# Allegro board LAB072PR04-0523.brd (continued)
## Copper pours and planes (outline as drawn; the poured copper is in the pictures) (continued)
BST_5V on TOP (solid shape): 51.49,27.49 51.49,26.47 51.43,26.41 51.43,25.01 51.3,24.88 50.66,24.88 50.44,25.1 50.44,25.61 51.24,26.41 51.24,27.42 51.36,27.55 51.43,27.55
CHAGER_SRC on TOP (solid shape): 40.19,42.47 40.19,34.98 39.81,34.6 39.81,29.26 39.68,29.14 35.36,29.14 35.23,29.26 35.23,33.84 35.62,34.22 36.89,34.22 37.14,34.47 37.14,35.49 37.27,35.61 37.27,39.42 37.01,39.68 30.92,39.68 30.54,40.06 30.54,42.34 30.92,42.73 39.93,42.73
CHAGER_SRC on BOTTOM (solid shape): 40.82,39.17 40.82,35.61 39.81,34.6 37.39,34.6 37.14,34.85 37.14,39.17 36.76,39.55 31.04,39.55 30.54,40.06 30.54,41.58 31.04,42.09 33.2,42.09 33.84,42.73 37.27,42.73
CHG_LGATE on TOP (solid shape): 28.38,35.99 28.38,34.98 28.12,34.72 26.85,34.72 26.6,34.98 26.6,35.99 26.85,36.25 28.12,36.25
CHG_LGATE on BOTTOM (solid shape): 31.69,17.86 31.69,17.02 31.95,16.77 31.95,15.78 31.89,15.73 31.8,15.73 31.74,15.79 31.74,16.57 31.51,16.8 31.32,16.8 31.17,16.95 31.17,17.87 31.26,17.97 31.58,17.97
CHG_LGATE on IN3 (solid shape): 31.42,19.23 31.42,18.34 31.81,17.96 31.81,16.94 31.55,16.69 31.04,16.69 30.41,17.33 30.41,19.61 31.04,19.61
CHG_LGATE on IN3: 27.11,33.84 27.11,34.47 26.6,34.98 26.6,35.99 26.85,36.25 27.87,36.25 28.12,35.99 28.12,33.96 28,33.84
CHG_SW on TOP (solid shape): 34.54,18.98 34.54,17.26 34.22,16.94 33.9,16.94 33.84,17.01 33.84,17.96 33.52,18.28 33.52,18.98 33.58,19.04 34.47,19.04
CHG_SW on TOP (solid shape): 34.6,33.71 34.6,30.66 34.35,30.41 33.2,30.41 32.82,30.03 32.82,28.5 33.08,28.25 34.8,28.25 35.23,27.82 35.23,23.55 34.85,23.17 29.52,23.17 29.14,23.55 29.14,24.44 27.36,26.22 27.36,33.84 27.61,34.09 34.22,34.09
CHG_SW on BOTTOM (solid shape): 34.36,17.99 34.36,17.02 34.08,16.75 33.74,16.75 33.55,16.55 33.55,15.79 33.49,15.73 33.4,15.73 33.34,15.78 33.34,16.6 33.83,17.09 33.83,17.98 33.95,18.1 34.25,18.1
CHG_SW on BOTTOM (solid shape): 33.58,32.92 33.58,30.79 33.05,30.25 33.05,28.48 33.84,27.69 38.49,27.69 38.92,27.26 38.92,21.77 38.28,21.14 31.93,21.14 31.3,21.77 31.3,32.82 31.73,33.25 33.25,33.25
CHG_SW on IN1 (solid shape): 34.85,17.07 34.6,16.82 33.96,16.82 33.84,16.94 33.84,19.74 34.85,19.74
CHG_SW on IN1 (solid shape): 38.03,22.91 38.03,22.28 37.77,22.02 36.57,22.02 36.21,21.66 35.92,21.66 35.47,22.12 35.47,22.38 36.13,23.04 37.9,23.04
CHG_UGATE on TOP (solid shape): 34.54,29.71 34.54,28.56 34.41,28.44 33.39,28.44 33.14,28.69 33.14,29.58 33.39,29.83 34.41,29.83
CHG_UGATE on BOTTOM (solid shape): 33.59,18.02 33.59,17.09 33.14,16.65 33.14,15.79 33.09,15.73 33,15.73 32.94,15.79 32.94,16.9 33.07,17.02 33.07,17.99 33.18,18.1 33.51,18.1
CHG_UGATE on IN3 (solid shape): 33.71,18.98 33.71,16.94 33.58,16.82 33.2,16.82 33.08,16.94 33.08,17.33 32.89,17.51 32.89,19.04 33.08,19.23 33.46,19.23
CHG_UGATE on IN3: 34.47,29.26 33.33,29.26 33.08,29.01 33.08,28.5 33.33,28.25 33.96,28.25 34.73,27.48 35.12,27.48 35.44,27.8 35.44,28.3
DH_1.35V on TOP (solid shape): 68.64,33 68.64,32.06 68.51,31.93 67.62,31.93 67.49,32.06 67.49,32.54 68.03,33.07 68.56,33.07
DH_1.35V on BOTTOM (solid shape): 62.03,33.58 62.03,33.07 61.51,32.55 60.91,32.55 60.87,32.52 59.88,32.52 59.82,32.58 59.82,32.66 59.88,32.72 60.79,32.72 61.4,33.32 61.4,33.58 61.52,33.71 61.9,33.71
DH_1.35V on IN3 (solid shape): 68.79,32.59 68.79,31.7 68.66,31.57 67.64,31.57 66.88,32.34 66.5,32.34 66.5,33.1 68.28,33.1
DH_1.35V on IN3: 61.82,33.87 60.89,32.95 60.89,32.57 61.14,32.31 61.4,32.31 62.39,33.3 62.39,33.61 62.12,33.87
DL_1.35V on BOTTOM (solid shape): 60.43,34.77 60.43,33.88 59.92,33.37 59.92,33.37 59.75,33.2 59.59,33.2 59.54,33.24 59.54,34.2 59.92,34.58 59.92,34.77 60.05,34.9 60.3,34.9
DL_1.35V on IN3 (solid shape): 60.68,33.81 60.56,33.68 60.02,33.68 59.92,33.78 59.92,35.61 60.68,35.61
DL_1.35V on IN3 (solid shape): 64.98,35.92 64.98,35.08 64.77,34.88 63.68,34.88 63.43,35.13 63.43,35.89 63.94,35.89 64.19,36.15 64.75,36.15
DL_1.35V on TOP: 64.03,36.02 64.03,35.07 64.15,34.94 64.98,34.94 65.1,35.07 65.1,36.02 64.98,36.15 64.15,36.15
GPU_B+ on TOP (solid shape): 73.08,44.88 73.08,37.35 72.9,37.17 71.9,37.17 71.75,37.32 71.75,37.93 71.21,38.47 70.89,38.47 70.57,38.15 60.25,38.15 60.15,38.25 60.15,39.78 59.87,40.06 56.7,40.06 56.44,40.31 56.44,44.38 57.08,45.01 61.14,45.01 61.4,44.76 61.4,44.12 61.78,43.74 62.67,43.74 62.84,43.56 66.55,43.56 66.73,43.74 67.49,43.74 67.62,43.87 67.62,44.25 68.51,45.14 72.83,45.14
GPU_B+ on BOTTOM (solid shape): 62.92,43.49 66.48,43.49 66.73,43.74 67.24,43.74 67.37,43.61 67.37,41.53 67.03,41.2 62.39,41.2 62.01,41.58 62.01,43.59 62.16,43.74 62.67,43.74
GPU_PSI on BOTTOM (solid shape): 49.65,45.52 49.65,43.36 49.84,43.17 50.03,43.17 50.09,43.11 50.09,42.6 50.03,42.53 49.52,42.53 49.39,42.66 49.39,43.11 49.27,43.23 49.27,45.46 49.39,45.58 49.59,45.58
GPU_REFADJ on BOTTOM (solid shape): 48.63,45.52 48.63,44.38 48.51,44.25 48.51,43.68 48.25,43.42 47.68,43.42 47.42,43.16 47.42,42.57 47.37,42.52 46.86,42.52 46.79,42.6 46.79,43.36 47.43,44 47.71,44 48.19,44.47 48.19,45.39 48.38,45.58 48.57,45.58
GPU_VID on BOTTOM (solid shape): 49.14,45.52 49.14,43.17 49.2,43.11 49.2,42.6 49.14,42.53 47.74,42.53 47.68,42.6 47.68,43.04 47.87,43.23 48.38,43.23 48.63,43.49 48.63,44.19 48.82,44.38 48.82,45.52 48.89,45.58 49.08,45.58
INT-SPK-L+ on TOP (solid shape): 204.27,3.48 204.27,1.83 204.14,1.7 203.38,1.7 203.26,1.83 203.25,3.35 203.25,3.48 203.32,3.55 204.21,3.55
INT-SPK-L+ on IN3 (solid shape): 188.11,26.29 188.11,24.64 187.53,24.06 187.25,24.06 187.13,24.18 187.13,26.34 187.36,26.58 187.83,26.58
INT-SPK-L- on TOP (solid shape): 206.18,3.47 206.18,1.96 205.92,1.7 205.41,1.7 205.16,1.96 205.16,3.36 205.16,3.52 205.22,3.58 206.06,3.58
INT-SPK-L- on IN3 (solid shape): 187,25.61 187,23.93 186.87,23.8 186.49,23.8 186.36,23.93 186.36,25.12 186.04,25.44 185.73,25.44 185.21,25.96 185.02,25.96 184.98,26 184.98,26.98 185.64,26.98
INT-SPK-R+ on TOP (solid shape): 209.1,3.47 209.1,2.97 208.97,2.85 206.81,2.85 206.65,3.01 206.65,3.5 206.74,3.6 208.97,3.6
INT-SPK-R+ on IN3 (solid shape): 208.21,3.74 208.21,2.97 208.08,2.85 206.58,2.85 206.51,2.92 206.51,3.74 206.63,3.86 208.08,3.86
INT-SPK-R+ on IN3 (solid shape): 185.09,24.95 185.09,24.56 184.84,24.31 184.46,24.31 184.08,24.69 183.95,24.69 183.82,24.82 183.82,25.45 184.08,25.71 184.33,25.71
INT-SPK-R+ on TOP: 184.21,25.45 184.46,25.45 185.22,24.69 185.22,24.56 185.48,24.31 185.48,23.8 185.35,23.68 185.29,23.68 184.21,24.76 184.21,24.76 184.07,24.9 184.07,25.31
INT-SPK-R- on TOP (solid shape): 212.6,7.39 212.6,5.85 212.38,5.63 211.08,5.63 210.98,5.72 210.98,7.39 211.14,7.55 212.44,7.55
INT-SPK-R- on IN3 (solid shape): 186.11,25.07 186.11,23.68 185.86,23.42 185.35,23.42 185.09,23.68 185.09,24.06 185.35,24.31 185.35,24.95 185.6,25.2 185.98,25.2
INT-SPK-R- on IN3 (solid shape): 212.15,7.42 212.15,6.02 211.46,5.33 210.28,5.33 210.04,5.57 210.04,6.05 210.88,6.89 210.88,7.42 211,7.55 212.02,7.55
ISUMP on BOTTOM (solid shape): 70.82,111.62 70.82,109.5 70.65,109.33 69.33,109.33 69.29,109.37 69.29,111.56 69.46,111.73 70.7,111.73
LG_+1.35DGPU on TOP (solid shape): 41.61,53.88 41.61,53.39 41.41,53.19 40.21,53.19 39.78,52.76 38.82,52.76 38.66,52.91 38.66,53.72 38.82,53.88 39.96,53.88 40.19,54.1 41.38,54.1
LG_+1.35DGPU on TOP: 48.16,56.9 48.82,56.9 48.95,57.03 48.95,57.69 48.8,57.84 47.93,57.84 47.81,57.71 47.81,57.25
LG_+1.35DGPU on IN1: 46.41,57.97 48.95,57.97 49.08,57.84 49.08,57.33 48.95,57.2 46.41,57.2
LGATE on TOP (solid shape): 65.2,109.8 65.2,109.05 65.12,108.98 63.85,108.98 63.3,109.53 63.3,109.78 63.43,109.91 65.09,109.91
LGATE on BOTTOM (solid shape): 65.84,121.59 65.84,120.45 65.59,120.2 64.7,120.2 64.45,120.45 64.45,121.09 64.44,121.09 64.44,121.59 64.6,121.75 65.68,121.75
LGATE on IN2: 63.43,110.92 64.95,110.92 65.21,110.67 65.21,109.65 64.83,109.27 63.43,109.27 63.17,109.53 63.17,110.67
LGATE on IN2: 66.22,120.83 65.97,120.58 64.57,120.58 64.32,120.83 64.32,121.85 64.57,122.1 65.97,122.1 66.22,121.85
LX_1.05V on TOP (solid shape): 100.39,118.53 100.39,117 100.11,116.73 98.85,116.73 98.8,116.78 98.8,118.47 99.04,118.71 100.21,118.71
LX_1.05V on BOTTOM (solid shape): 104.37,119.37 104.37,112.7 102.84,112.7 102.59,112.95 102.59,114.48 102.02,115.05 101.25,115.05 98.9,117.4 97.71,117.4 97.71,118.57 98.94,118.57 99.35,118.97 99.35,119.3 99.8,119.75 101.64,119.75 101.76,119.87 103.86,119.87
LX_3V on TOP (solid shape): 46.16,36.12 46.16,34.91 46.79,34.28 46.79,32.12 46.6,31.93 43.87,31.93 43.74,32.06 43.74,33.38 43.62,33.5 41.57,33.5 41.39,33.68 41.39,36.12 41.77,36.5 45.78,36.5
LX_3V on TOP (solid shape): 53.01,32.44 53.01,31.17 52.89,31.04 52.38,31.04 52.06,30.72 51.87,30.53 51.87,29.58 51.81,29.52 51.74,29.52 51.68,29.58 51.68,30.72 51.55,30.85 51.55,31.74 51.68,31.87 51.68,32.37 51.87,32.57 52.89,32.57
LX_3V on BOTTOM (solid shape): 46.16,36.12 46.16,31.23 45.97,31.04 41.52,31.04 41.27,31.3 41.27,36.25 41.52,36.5 45.78,36.5
LX_3V on IN3 (solid shape): 46.56,35.87 46.56,34.83 46.38,34.65 45.6,34.65 45.39,34.85 45.39,35.66 45.72,35.99 46.44,35.99
LX_3V on IN3 (solid shape): 52.38,32.82 52.51,32.82 52.63,32.69 52.63,32.57 53.14,32.06 53.14,31.3 52.89,31.04 52.51,31.04 51.74,31.8 51.74,32.82 52,33.07 52,33.2
LX_5V on TOP (solid shape): 51.87,27.49 51.87,26.41 52.06,26.22 52.06,26.02 52.38,25.71 52.38,24.6 52.32,24.54 51.71,24.54 51.55,24.69 51.55,26.28 51.68,26.41 51.68,27.49 51.74,27.55 51.81,27.55
LX_5V on TOP (solid shape): 46.92,24.32 46.92,22.02 46.92,22.02 46.92,19.99 46.66,19.74 40.63,19.74 40.31,20.06 40.31,22.51 40.61,22.8 42.36,22.8 42.48,22.68 42.48,22.3 42.16,21.97 42.16,21.39 42.35,21.2 43.43,21.2 43.74,21.52 43.74,22.41 43.57,22.58 43.57,23.89 44.07,24.39 46.84,24.39
LX_5V on BOTTOM (solid shape): outline of 89 points within 40.82,19.8 46.79,24.82
LX_5V on IN1 (solid shape): 52.19,26.22 52.19,24.42 52.01,24.24 51.56,24.24 51.37,24.42 51.37,26.32 51.46,26.41 52,26.41
LX_5V on IN1 (solid shape): 46.77,20.77 47.68,20.77 47.81,20.64 47.81,20.06 47.73,19.98 46.99,19.98 46.69,19.67 46.44,19.67 46.28,19.83 46.28,20.67 46.42,20.8 46.73,20.8
PBATT+_C on TOP: 15.55,28.25 15.3,28.5 13.64,28.5 13.5,28.64 13.5,31.79 14.15,32.44 14.15,32.95 14.79,33.58 16.95,33.58 17.84,34.47 19.23,34.47 20.25,33.45 20.25,28.37 20.12,28.25
PHASE on TOP (solid shape): 64.99,111.75 64.99,110.71 65.7,110 65.7,109.04 65.63,108.98 65.51,108.98 65.44,109.05 65.44,109.87 65.14,110.16 63.05,110.16 62.79,110.42 62.79,111.75 62.89,111.86 64.88,111.86
PHASE on BOTTOM (solid shape): 60.25,120.86 60.25,120.48 60,120.23 59.01,120.23 58.48,119.69 58.09,119.69 57.97,119.81 57.97,120.32 58.76,121.12 60,121.12
PHASE on IN1 (solid shape): 64.06,111.81 64.06,111.05 63.94,110.92 61.14,110.92 61.14,111.94 63.94,111.94
PHASE on IN1 (solid shape): 59.11,120.7 59.11,120.07 57.08,118.04 57.08,117.53 56.06,117.53 56.06,118.55 58.35,120.83 58.98,120.83
RING2 on TOP (solid shape): 186.12,17.16 186.12,15.81 185.6,15.29 184.89,15.29 184.87,15.32 184.87,16.03 184.94,16.11 185.75,16.11 185.92,16.27 185.92,17.16 185.98,17.22 186.06,17.22
RING2 on BOTTOM: 188.24,14.8 187.17,15.87 186.25,15.87 185.67,15.29 183.82,15.29 183.57,15.55 183.57,16.46 184.3,17.18 187.9,17.18 189.03,16.06 192.37,16.06 192.55,15.88 192.55,15 192.35,14.8
RING2_L on BOTTOM: 192.92,14.79 192.74,14.97 192.74,15.99 192.9,16.15 193.2,16.15 194.14,15.22 196.6,15.22 197.55,16.16 197.55,19.84 196.97,20.42 196.97,20.91 197.08,21.02 198.86,21.02 199.03,21.19 200.03,21.19 200.19,21.03 200.19,20.45 200.19,20.45 200.1,20.37 199.65,20.37 198.63,19.35 198.63,17.45 198.81,17.27 198.81,15.56 197.37,14.12 193.73,14.12 193.06,14.79
SLEEVE on TOP (solid shape): 186.52,17.16 186.52,16.35 186.59,16.29 186.59,15.95 186.74,15.8 186.74,15.29 186.24,14.79 185.93,14.79 185.82,14.91 185.82,15.13 186.26,15.57 186.26,16.24 186.32,16.29 186.32,17.16 186.38,17.22 186.46,17.22
SLEEVE on BOTTOM: 186.9,13.28 186.29,13.9 182.43,13.9 182.05,13.52 181.79,13.52 181.67,13.64 181.67,14.4 182.3,15.04 185.67,15.04 186.35,15.71 186.62,15.71 187.88,14.45 192.39,14.45 192.51,14.33 192.51,13.41 192.38,13.28
SLEEVE_L on TOP (solid shape): 209.13,9.05 209.13,8 208.89,7.76 207.6,7.76 207.23,8.13 207.23,9.01 207.62,9.4 208.78,9.4
SLEEVE_L on TOP (solid shape): 200.06,9.07 201.39,9.07 201.57,8.89 201.57,8.27 201.36,8.06 198.85,8.06 197.93,8.98 197.93,9.51 198.4,9.97 199.15,9.97
SLEEVE_L on BOTTOM (solid shape): 193.92,13.48 196.51,13.48 196.65,13.45 196.79,13.48 197.48,13.48 198.43,12.54 198.43,10.85 199.82,9.46 200.28,9.46 200.51,9.24 200.51,8.14 200.4,8.03 198.88,8.03 197.41,9.49 197.41,11.7 197.08,12.03 193.27,12.03 192.72,12.58 192.72,14.17 192.79,14.24 193.16,14.24
SPK_L1-_CONN on TOP (solid shape): 206.94,6.02 206.94,5.13 206.81,5.01 206.3,5.01 206.18,4.88 206.18,3.9 206.04,3.76 205.27,3.76 205.16,3.88 205.16,6.02 205.29,6.15 206.81,6.15
SPK_L1-_CONN on BOTTOM (solid shape): 206.81,8.38 206.81,5.84 207.14,5.51 207.14,5.26 207.01,5.13 206.5,5.13 206.02,5.62 206.02,8.33 206.25,8.56 206.63,8.56
SPK_L2+_CONN on BOTTOM (solid shape): 205.68,8.35 205.68,7.03 204.78,6.12 204.53,6.02 204.42,5.77 204,5.35 201.68,5.35 201.41,5.62 201.41,6.18 201.84,6.62 203.79,6.62 204.63,7.46 204.63,8.41 204.81,8.59 205.44,8.59
SPK_L2+_CONN on TOP: 203.26,4.88 203,5.13 201.5,5.13 201.32,5.31 201.32,6 201.48,6.15 204.02,6.15 204.14,6.02 204.14,5.13 204.27,5.01 204.27,3.86 204.18,3.77 203.33,3.77 203.26,3.85
SPK_R1-_CONN on TOP (solid shape): 212.15,5.39 212.15,4.5 211.33,3.68 210.16,3.68 209.48,4.37 209.48,5.26 209.61,5.39 211,5.39 211.07,5.46 212.07,5.46
SPK_R1-_CONN on BOTTOM: 208.6,8.56 209.11,8.56 209.29,8.38 209.29,7.03 210.45,5.87 210.45,4.38 210.28,4.21 209.57,4.21 209.42,4.36 209.42,5.53 208.4,6.55 208.4,8.36
SPK_R2+_CONN on TOP (solid shape): 208.21,6.02 208.87,6.02 209.1,5.79 209.1,3.9 208.97,3.77 208.2,3.77 208.06,3.91 208.06,4.57 207.25,4.57 207.07,4.75 207.07,6.02 207.19,6.15 208.08,6.15
SPK_R2+_CONN on BOTTOM (solid shape): 208.05,8.4 208.05,6.63 208.41,6.28 208.41,5.77 208.28,5.64 207.25,5.64 207.08,5.81 207.08,8.33 207.32,8.56
SW_1.35V on BOTTOM (solid shape): 64.06,34.72 64.39,34.72 65.41,35.74 68.35,35.74 68.63,35.46 68.63,32.94 68.28,32.59 67.24,32.59 66.93,32.29 66.93,30.76 66.4,30.23 63.76,30.23 63.43,30.56 63.43,34.22 63.17,34.47 61.59,34.47 61.36,34.25 61.3,34.2 61.25,34.13 61.24,34.12 61.22,34 61.24,33.88 61.24,33.36 60.75,32.87 59.83,32.87 59.77,32.93 59.77,33.01 59.96,33.2 59.97,33.2 60.59,33.82 60.59,35.31 61.02,35.74 63.05,35.74
SW_1.35V on TOP: 68.64,34.85 68.64,33.33 68.51,33.2 67.87,33.2 66.98,32.31 66.98,31.3 66.1,30.41 63.56,30.41 62.29,31.68 62.29,32.18 62.03,32.44 62.03,33.96 62.79,34.72 67.62,34.72 67.87,34.98 68.51,34.98
SW_+1.35DGPU on TOP (solid shape): 38.28,53.27 38.28,47.88 37.98,47.58 35.06,47.58 34.07,48.57 34.07,51.82 34.97,52.72 35.2,52.72 35.93,53.46 38.09,53.46
SW_+1.35DGPU on BOTTOM (solid shape): 38.41,51.11 38.41,47.68 38.28,47.55 34.37,47.55 34.09,47.83 34.09,50.85 34.6,51.36 38.16,51.36
SW_+1.35DGPU on TOP: 47.87,56.2 48.73,56.2 48.75,56.18 48.75,55.96 48.72,55.92 47.89,55.92 47.64,55.67 47.17,55.67 47.06,55.55 46.92,55.55 46.66,55.3 46.66,54.66 46.54,54.54 45.9,54.54 45.78,54.66 45.78,55.68 45.9,55.81 46.54,55.81 46.66,55.93 46.66,56.06 46.92,56.31 47.75,56.31
SW_+1.35DGPU on IN2: 45.78,56.44 47.93,56.44 48,56.38 48,55.74 47.93,55.68 45.78,55.68
SW_CPU2 on TOP (solid shape): 70.73,121.08 70.73,118.62 70.38,118.27 68.77,118.27 68.63,118.41 68.63,121.31 68.82,121.5 70.3,121.5
SW_CPU2 on BOTTOM (solid shape): 71.05,121.07 71.05,118.09 68.7,118.09 68.7,117.29 71.05,117.29 71.05,114.48 70.54,113.97 64.86,113.97 64.57,114.26 64.57,119.46 64.81,119.7 65.73,119.7 67.37,121.34 70.78,121.34
U2_BOOT1 on BOTTOM (solid shape): 51.17,45.52 51.17,45.01 53.01,43.17 53.01,42.28 52.89,42.15 52.25,42.15 52.06,42.34 52.06,43.17 50.86,44.38 50.86,45.52 50.92,45.58 51.11,45.58
U2_BOOT2 on BOTTOM (solid shape): 52.96,51.06 52.96,50.29 52.68,50.01 52.57,50.01 52.09,49.53 51.95,49.53 51.52,49.11 51.52,48.97 51.04,48.48 50.93,48.48 50.86,48.56 50.86,49.46 51.11,49.71 51.35,49.71 51.43,49.71 52,50.28 52,50.92 52.26,51.18 52.84,51.18
U2_LGATE1 on TOP (solid shape): 67.87,49.2 67.87,48.19 67.62,47.93 66.6,47.93 66.48,48.06 66.48,49.2 66.6,49.33 67.75,49.33
U2_LGATE1 on BOTTOM (solid shape): 54.28,46.66 54.28,46.15 54.19,46.06 52.41,46.06 52.38,46.09 51.3,46.09 51.17,46.22 51.17,46.41 51.24,46.47 52.38,46.47 52.44,46.54 52.95,46.54 53.14,46.73 54.22,46.73
U2_LGATE1 on IN2 (solid shape): 67.87,48.57 67.87,47.93 67.75,47.81 66.35,47.81 66.35,48.31 66.73,48.69 67.75,48.69
U2_LGATE1 on IN2 (solid shape): 54.03,46.28 54.03,45.58 53.52,45.58 53.2,45.9 52.44,45.9 52.32,46.03 52.32,46.47 52.38,46.54 52.95,46.54 53.14,46.73 53.59,46.73
U2_LGATE2 on TOP (solid shape): 64.06,52.5 64.06,52.12 63.81,51.87 61.65,51.87 61.46,52.06 61.46,52.31 61.9,52.76 63.81,52.76
U2_LGATE2 on BOTTOM (solid shape): 53.46,47.61 53.46,47.3 53.31,47.14 52.96,47.14 52.68,47.42 52.57,47.42 52.38,47.61 51.24,47.61 51.17,47.68 51.17,47.87 51.3,48 53.08,48
U2_LGATE2 on IN2 (solid shape): 64.19,52.5 64.19,52 64.06,51.87 61.4,51.87 61.4,52.63 64.06,52.63
U2_LGATE2 on IN2 (solid shape): 54.82,48.54 53.41,47.12 53.01,47.12 52.76,47.37 52.46,47.37 52.25,47.58 52.25,47.96 52.46,48.16 53.37,48.16 54.28,49.08
U2_PHASE1 on TOP (solid shape): 73.16,55.37 73.16,46.08 72.7,45.62 69.7,45.62 69.04,46.28 69.04,47.81 68.18,48.67 68.18,53.57 68.56,53.95 68.56,55.98 68.74,56.16 72.37,56.16
U2_PHASE1 on BOTTOM (solid shape): 72.81,55.49 72.81,50.84 72.32,50.35 70.06,50.35 69.8,50.6 67.11,50.6 66.73,50.98 66.73,54.66 68,55.93 72.37,55.93
U2_PHASE1 on BOTTOM (solid shape): 54.47,45.71 54.47,44.95 54.28,44.76 52.38,44.76 52.25,44.88 52.25,45.27 52,45.52 51.36,45.52 51.17,45.71 51.17,45.84 51.24,45.9 54.28,45.9
U2_PHASE1 on IN3 (solid shape): 70.24,48.64 70.24,47.32 70.08,47.17 69.42,47.17 69.27,47.32 69.27,48.67 69.4,48.8 70.08,48.8
U2_PHASE1 on IN3 (solid shape): 53.8,45.24 53.8,44.68 53.55,44.43 52.33,44.43 52.07,44.68 52.07,45.34 52.23,45.49 53.55,45.49
U2_PHASE2 on TOP (solid shape): 60.76,55.81 60.76,47.68 61.27,47.17 61.27,45.9 61.02,45.65 58.35,45.65 58.09,45.9 58.09,47.17 57.46,47.81 56.32,47.81 56.19,47.93 56.19,55.81 56.44,56.06 60.51,56.06
U2_PHASE2 on BOTTOM (solid shape): 62.29,55.55 62.29,50.98 60.89,49.58 58.09,49.58 56.06,51.62 56.06,54.92 57.08,55.93 61.9,55.93
U2_PHASE2 on BOTTOM (solid shape): 53.58,48.74 54.3,48.74 54.35,48.69 54.35,47.87 54.28,47.81 53.46,47.81 53.14,48.12 51.24,48.12 51.17,48.19 51.17,48.31 51.65,48.79 51.65,49.06 52,49.41 52.91,49.41
U2_PHASE2 on IN2 (solid shape): 58.35,55.93 58.35,55.43 58.22,55.3 56.32,55.3 56.32,56.06 58.22,56.06
U2_PHASE2 on IN2 (solid shape): 53.19,49.35 53.19,48.87 53.04,48.72 51.92,48.72 51.72,48.92 51.72,49.33 51.99,49.6 52.95,49.6
U2_UGATE1 on TOP (solid shape): 68,46.08 68,45.19 67.85,45.04 66.96,45.04 66.37,45.62 66.37,46.31 66.48,46.41 67.67,46.41
U2_UGATE1 on BOTTOM (solid shape): 50.6,45.52 50.6,44.44 51.43,43.61 51.43,43.36 51.36,43.3 50.86,43.3 50.41,43.74 50.41,43.74 50.41,44.12 50.35,44.19 50.35,45.52 50.41,45.58 50.54,45.58
U2_UGATE1 on IN2 (solid shape): 68.13,46.28 68.13,44.38 67.49,43.74 67.11,43.74 67.11,44.5 67.37,44.76 67.37,46.28 67.49,46.41 68,46.41
U2_UGATE1 on IN2 (solid shape): 51.36,43.93 52.13,43.93 52.19,43.87 52.19,43.23 52.13,43.17 50.98,43.17 50.41,43.74 50.41,44.25 50.47,44.31 50.98,44.31
U2_UGATE2 on TOP (solid shape): 52.01,50.71 52.01,50.21 51.51,49.71 51.24,49.71 51.22,49.7 50.85,49.7 50.66,49.89 50.66,50.31 51.2,50.85 51.87,50.85
U2_UGATE2 on BOTTOM (solid shape): 51.82,50.76 51.82,50.36 51.3,49.84 51.03,49.84 50.66,49.47 50.66,48.5 50.6,48.44 50.41,48.44 50.35,48.5 50.35,49.81 50.66,50.12 50.66,50.31 51.37,51.02 51.55,51.02
UG_3V on TOP (solid shape): 41.2,34.33 41.2,33.61 41.1,33.5 40.59,33.5 40.42,33.33 40.19,33.33 40.06,33.45 40.06,34.32 40.26,34.52 41.01,34.52
UG_3V on TOP (solid shape): 50.47,30.53 50.98,30.53 51.05,30.47 51.05,29.58 50.98,29.52 50.92,29.58 50.78,29.58 50.35,29.58 49.56,30.37 49.56,30.63 49.84,30.91 50.09,30.91
UG_3V on IN3 (solid shape): 50.73,31.04 50.73,29.77 50.6,29.64 50.09,29.64 49.71,30.03 49.71,30.79 50.09,31.17 50.6,31.17
UG_3V on IN3 (solid shape): 41.33,34.34 41.33,33.1 41.25,33.02 40.16,33.02 39.93,33.25 39.93,34.34 40.14,34.55 41.13,34.55
UG_5V on TOP (solid shape): 51.11,27.49 51.11,26.66 50.73,26.28 50.35,26.28 50.22,26.41 50.22,27.23 50.41,27.42 50.79,27.42 50.92,27.55 51.05,27.55
UG_5V on TOP (solid shape): 43.49,22.4 43.49,21.52 43.3,21.33 42.54,21.33 42.35,21.52 42.35,21.77 42.72,22.14 42.72,22.74 42.78,22.8 43.09,22.8
UG_5V on IN1 (solid shape): 44.76,22.28 44.51,22.28 43.62,21.39 42.47,21.39 42.35,21.52 42.35,21.77 43.62,23.04 44.76,23.04
UG_5V on IN1 (solid shape): 50.93,27.32 50.93,25.5 50.78,25.35 50.16,25.35 50.08,25.43 50.08,27.35 50.16,27.42 50.83,27.42
UG_+1.35DGPU on TOP (solid shape): 38.16,47.17 38.16,46.6 37.9,46.34 36.87,46.34 36.71,46.51 36.71,47.3 36.81,47.4 37.93,47.4
UG_+1.35DGPU on IN2 (solid shape): 38.18,47.53 38.18,46.31 38.03,46.15 36.76,46.15 36.63,46.28 36.63,46.79 37.52,47.68 38.03,47.68
UG_+1.35DGPU on TOP: 47.93,55.7 48.75,55.7 48.79,55.66 48.79,55.44 48.77,55.42 48.08,55.42 47.87,55.22 47.87,55.04 47.75,54.91 46.84,54.91 46.73,55.03 46.73,55.28 46.9,55.45 47.68,55.45
UG_+1.35DGPU on IN2: 46.69,55.5 47.91,55.5 48.06,55.35 48.06,54.79 47.91,54.64 46.69,54.64 46.49,54.84 46.49,55.3
UGATE on TOP: 66.07,110.31 66.2,110.19 66.2,109.04 66.12,108.97 65.99,108.97 65.94,109.02 65.94,109.93 65.17,110.71 65.17,111.6 65.22,111.65 66.05,111.65 66.07,111.62
N17002616 on BOTTOM (solid shape): 54.41,51.39 54.41,49.27 54.28,49.14 53.4,49.14 53.32,49.21 53.32,51.29 53.44,51.41 54.38,51.41
N17002633 on BOTTOM (solid shape): 54.54,44.31 54.54,42.34 54.41,42.22 53.65,42.22 53.46,42.41 53.46,44.31 53.52,44.38 54.47,44.38
N17607658 on BOTTOM (solid shape): 95,119.03 95.02,119.05 96.64,119.05 96.64,118.77 95.51,118.77 94.9,118.16 92.64,118.16 92.54,118.26 92.54,118.96 92.64,119.06 94.97,119.06
N18094610 on BOTTOM: 179,89.83 179,88.64 179.13,88.51 179.13,88.25 179.05,88.18 178.07,88.18 177.8,88.45 177.8,89.18 177.59,89.39 175.68,89.39 175.49,89.58 175.49,91.13 175.67,91.3 177.98,91.3 178.63,91.95 179.05,91.95 179.14,91.86 179.14,90.5 178.87,90.24 178.87,89.96
N18264318 on TOP (solid shape): 66.45,113.67 66.45,113.44 66.07,113.06 66.07,112.4 66.04,112.37 65.18,112.37 65.16,112.4 65.16,113.69 65.31,113.85 66.27,113.85
N18264318 on BOTTOM (solid shape): 60.25,119.59 60.25,119.08 60.13,118.96 59.62,118.96 58.73,118.07 58.35,118.07 58.22,118.19 58.22,118.58 59.37,119.72 60.13,119.72
N18264318 on IN1 (solid shape): 66.48,113.59 66.48,113.08 66.22,112.83 64.32,112.83 64.32,113.85 66.22,113.85
N18264318 on IN1 (solid shape): 59.49,119.31 59.49,118.67 58.98,118.16 58.98,116.64 57.97,116.64 57.97,118.67 58.73,119.43 59.36,119.43
N18299507 on TOP (solid shape): 49.47,29.45 50.73,29.45 50.79,29.39 50.79,29.25 50.75,29.21 48.29,29.21 47.17,30.33 46.59,30.33 46.41,30.51 46.41,31.42 46.54,31.55 47.38,31.55
N18300498 on TOP (solid shape): 44.91,25.62 44.91,25.12 44.78,25 44.33,25 44.19,25.14 43.87,25.14 43.8,25.21 43.8,26.21 43.87,26.28 44.25,26.28
N18300498 on TOP (solid shape): 50.79,27.74 50.79,27.68 50.73,27.61 50.35,27.61 49.95,27.22 49.95,26.89 49.49,26.43 49.49,25.76 49.35,25.62 48.95,25.62 48.87,25.69 48.87,26.72 48.88,26.74 48.89,26.76 48.93,26.8 48.97,26.87 49.74,27.64 49.72,27.65 49.72,27.75 49.84,27.87 50.66,27.87
N18300498 on IN1 (solid shape): 46,24.44 44.25,24.44 43.49,25.2 43.49,26.09 43.74,26.34 44.1,26.34
N18300498 on IN1 (solid shape): 49.93,27.2 49.93,26.85 48.79,25.7 48.51,25.7 48.17,26.04 48.16,26.08 48.17,26.11 48.17,26.26 49.43,27.52 49.62,27.52
N18525878 on TOP (solid shape): 68.89,47.3 68.89,46.15 68.64,45.9 68.38,45.9 67.49,46.79 66.35,46.79 66.22,46.92 66.22,47.55 66.35,47.68 68.51,47.68
N18526201 on TOP (solid shape): 57.46,46.92 57.46,45.77 56.82,45.14 54.92,45.14 54.79,45.27 54.79,46.03 55.05,46.28 56.06,46.28 56.82,47.04 57.33,47.04
N19365430 on TOP (solid shape): 67.78,120.24 67.78,118.35 67.54,118.11 65.69,118.11 65.38,118.43 65.38,120.01 65.75,120.38 67.63,120.38
N20469401 on TOP (solid shape): 20.71,40.9 20.71,39.65 20.5,39.44 19.88,39.44 19.78,39.53 19.78,40.96 19.88,41.06 20.56,41.06
N20617538 on TOP: 37.8,117.73 37.8,115.14 37.97,114.97 39.07,114.97 39.37,115.27 39.37,117.54 39.04,117.87 37.94,117.87
N20617589 on TOP: 36.56,117.41 35.03,117.41 34.86,117.58 34.86,118.36 35.95,119.44 37.47,119.44 37.55,119.37 37.55,118.4
N47415217 on TOP (solid shape): 51.68,33.45 52.38,33.45 52.51,33.33 52.51,33.01 52.32,32.82 51.74,32.82 51.62,32.95 50.54,32.95 50.47,33.01 50.47,33.64 50.54,33.71 51.43,33.71
N47415258 on TOP (solid shape): 48.71,35.41 48.71,33.27 48.44,33.01 47.49,33.01 47.36,33.14 47.36,34.34 46.85,34.85 46.54,34.85 46.54,36.5 47.62,36.5
N47415272 on TOP: 47.68,22.79 48.7,22.79 48.82,22.66 48.82,19.87 48.7,19.74 47.68,19.74 47.55,19.87 47.55,22.66
N55200533 on TOP (solid shape): 199.06,71.81 199.06,68 198.3,67.24 198.3,66.86 199.06,66.09 199.06,63.55 198.94,63.43 198.18,63.43 198.05,63.55 198.05,66.09 197.41,66.73 197.41,67.36 198.18,68.13 198.18,71.55 197.29,72.44 195.38,72.44 195,72.06 195,67.74 195.25,67.49 195.25,66.86 195,66.6 193.86,66.6 193.6,66.86 193.6,67.49 193.98,67.87 193.98,72.06 195,73.08 197.79,73.08
N104716789 on BOTTOM (solid shape): 177.75,120.25 177.75,117.96 177.57,117.78 175.85,117.78 175.53,117.47 175.53,114.06 176.06,113.53 176.92,113.53 177.38,113.08 177.38,112.02 177.03,111.68 176.69,111.68 176.69,112.24 176.13,112.24 176.13,111.68 175.89,111.68 175.89,112.23 175.33,112.23 175.33,111.68 174.46,111.68 173.94,112.2 173.94,113.57 172.96,114.55 172.96,119.3 173.47,119.81 175.82,119.81 176.53,120.52 177.48,120.52

Small or netless copper shapes (teardrops, artwork), in the pictures only: 187 on TOP, 24 on BOTTOM, 5 on IN1, 26 on IN2

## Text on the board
Ref Des/Silkscreen Bottom: H24 | H23 | IO Board | H22 | H15 | HDMI | FAN | RTC | label area | Factory | DDR3L ONLY | VOLTAGE | DIMM A | DIMM B | LOW | NGFF | HDD | SPK | eDP+CCD | DB | BATT
User.Comments: Juce | LA-B072P | 2014-05-23 | 2015-05-23 | ZAL50/51/60/61 | 0.4(X03)
Ref Des/Silkscreen Top: Audio Jack | CRT | RJ45 | DC-In | KB | Backlight | USB3.0 | TP | FP | LED
COMPVAL_TYPE_TOP: trace Width | Width/Space | IN2 | IN3 | 45 ohm | 50 ohm | 82 ohm | 13.4 | 14.2 | 6.7 | 7.2 | 5 | 6.5 | 5.5 | 4 | 5.3 | 4.5 | SB_1_0mm-8L(4mil & 5mil 50ohm)_130923.pdf | 4.4/4 | 5.7/4 | 5.5/4.5 | 4/3.5 | 4.5/3.2 | 4/4.5 | 5.3/4.3 | 4.5/3.5 | 5.3/6 | 4/6.5 | 3.5/9 | 4.5/3.6 | Ref | L5/L7
DEVICE_TYPE_TOP: FIGURE | SIZE | 8.0 | 10.0 | 22.0 | 28.0 | 37.0 | 47.0 | 91.0 | 110.0 | 126.0 | 130.0 | 138.0 | 236.0 | 260.0 | 40.0 | 43.0 | 63.0 | 71.0 | 59.0x24.0 | 63.0x35.0 | 71.0x31.0 | 87.0x24.0 | 98.0x28.0 | 102.0x31.0 | 110.0x39.0 | 138.0x126.0 | 122.0x110.0 | DRILL CHART: TOP to BOTTOM | ALL UNITS ARE IN MILS | TOLERANCE | +3.0/-3.0 | +4.0/-4.0 | +2.0/-2.0 | PLATED | NON-PLATED | QTY | 3981 | 1153 | 19 | 33 | 8 | 9 | 1 | 6 | 2 | 3 | 5 | 7 | 4
User.24: B+ | GND | +1.35V_MEM_GFX | +3VS | GNDA | +VGA_CORE | +CPU_CORE | +1.05VS_PCH
